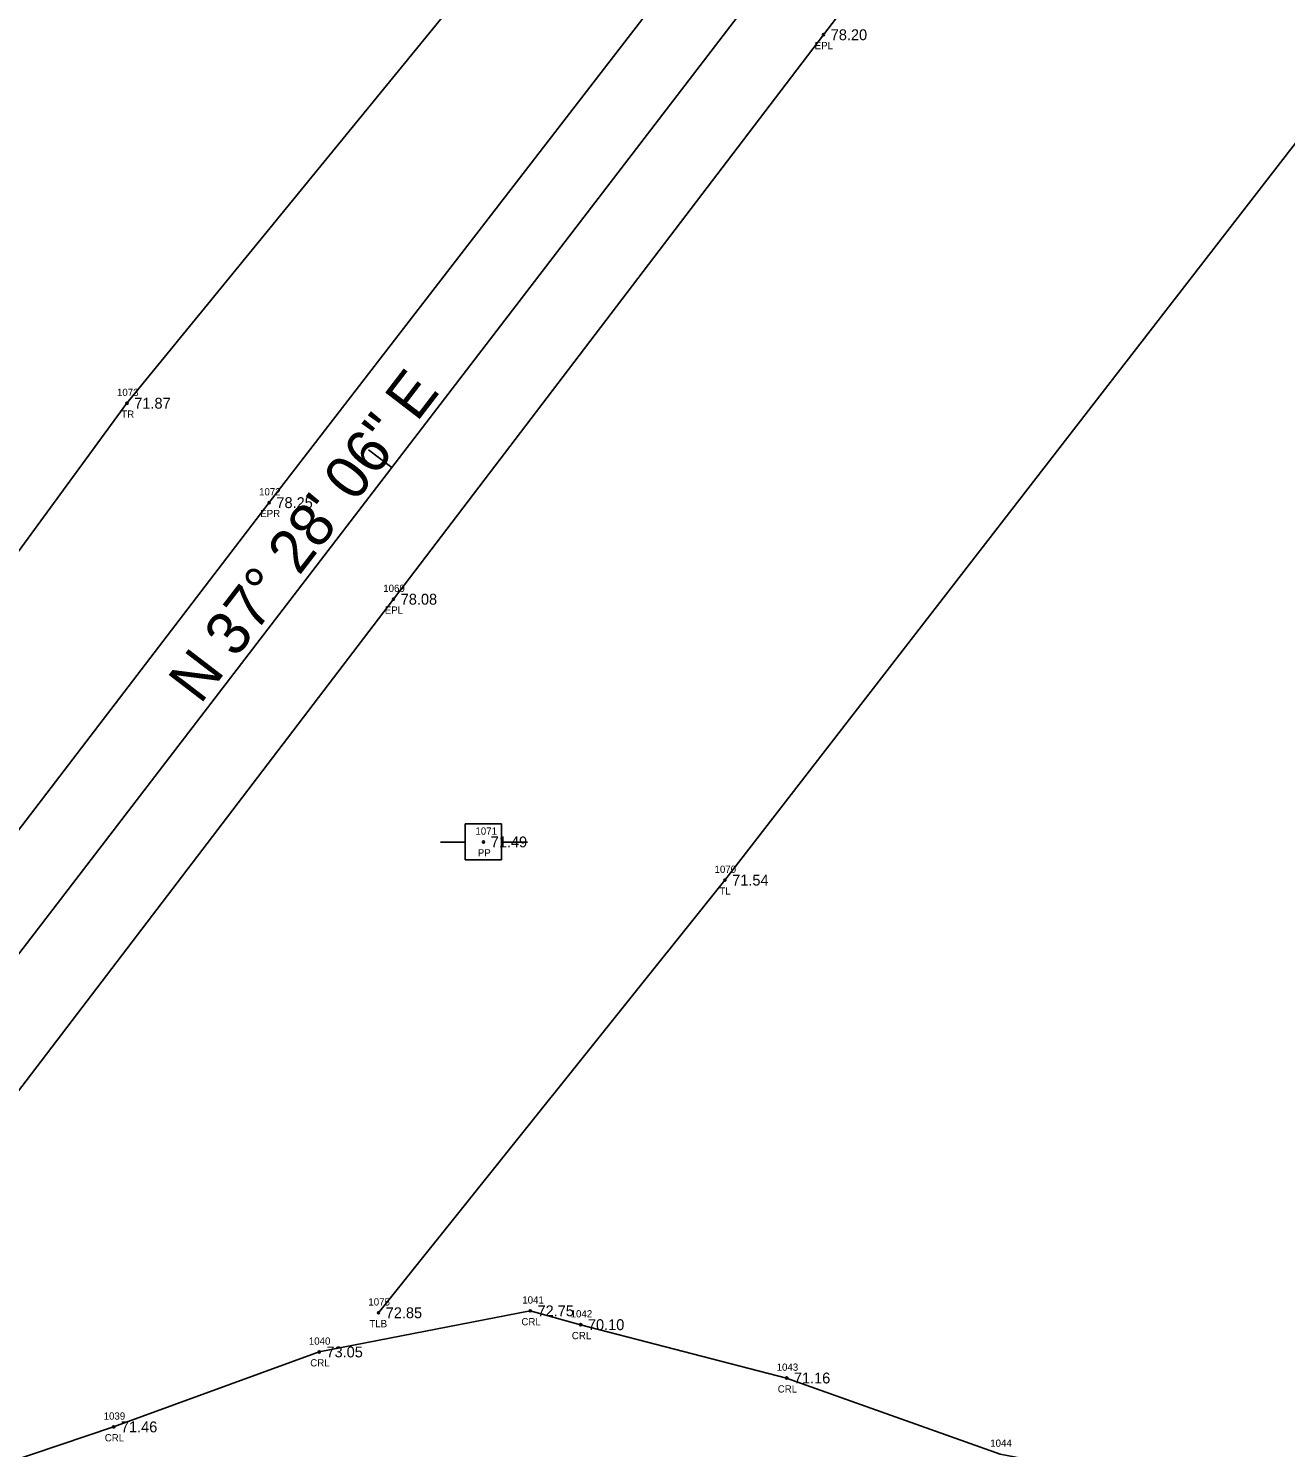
# Model space of a CAD drawing. Extents: x 2505249 to 2506333, y 912937 to 914171.
# Drawn here: x 2505870.1 to 2506043.4, y 913525.6 to 913721.3 of the extents above; entities that cross this region are included whole.
import ezdxf

# ---------------------------------------------------------------- set-up
doc = ezdxf.new("R2010")
doc.units = 0
for name, color, linetype in [('RD_EX_H2O', 7, 'Continuous'), ('RD_EX_H2O_txCode', 7, 'Continuous'), ('RD_EX_Road', 7, 'Continuous'), ('RD_EX_Road_txCode', 7, 'Continuous'), ('RD_EX_TX_H2O_ELEV', 7, 'Continuous'), ('RD_EX_TX_Road_ELEV', 7, 'Continuous'), ('RD_EX_TX_VEG_ELEV', 7, 'Continuous'), ('RD_EX_UT', 7, 'Continuous'), ('RD_EX_UT_txCode', 7, 'Continuous'), ('RD_EX_VEG', 7, 'Continuous'), ('RD_EX_VEG_txCode', 7, 'Continuous'), ('RD_HC_Cl', 7, 'Continuous'), ('RD_HC_Data', 7, 'Continuous'), ('RD_HC_Data_Tic', 7, 'Continuous'), ('RD_HC_Survey_ELEV', 7, 'Continuous'), ('RD_SMD_Locator', 7, 'Continuous')]:
    doc.layers.add(name, color=color, linetype=linetype)

msp = doc.modelspace()

# ---------------------------------------------------------------- linework, layer by layer
at = {"layer": 'RD_EX_H2O'}
msp.add_lwpolyline([(2505762.26, 913658.11), (2505746.15, 913644.25), (2505726.47, 913615.21), (2505674.21, 913628.01), (2505666.25, 913620.58), (2505714.6, 913592.15), (2505793.9, 913560.45), (2505801.32, 913552.8), (2505803.7, 913539.77), (2505832.63, 913516.96), (2505848.42, 913517.19), (2505881.86, 913528.44), (2505910.2, 913538.78), (2505939.3, 913544.45), (2505946.25, 913542.54), (2505974.65, 913535.18), (2506004.11, 913524.7), (2506052.03, 913515.47), (2506115.49, 913494.68), (2506138.05, 913548.89)], dxfattribs=at)
at = {"layer": 'RD_EX_Road'}
for points in [[(2506024.03, 913813.1), (2505962.01, 913732.06), (2505903.3, 913655.93), (2505840.88, 913574.4), (2505819.41, 913546.54), (2505814.19, 913542.64)], [(2506040.71, 913800.23), (2505979.73, 913720.47), (2505920.44, 913642.61), (2505859.42, 913562.61), (2505835.44, 913531.43), (2505833.77, 913527.25)]]:
    msp.add_lwpolyline(points, dxfattribs=at)
at = {"layer": 'RD_EX_UT'}
for p, q in [((2505935.34, 913611.64), (2505930.34, 913611.64)), ((2505930.34, 913611.64), (2505930.34, 913606.64)), ((2505935.34, 913606.64), (2505935.34, 913611.64)), ((2505926.91, 913609.08), (2505930.38, 913609.08)), ((2505935.27, 913609.08), (2505938.91, 913609.08)), ((2505930.34, 913606.64), (2505935.34, 913606.64))]:
    msp.add_line(p, q, dxfattribs=at)
at = {"layer": 'RD_EX_VEG'}
for points in [[(2506002.64, 913815.25), (2505883.7, 913669.64), (2505827.83, 913593.29), (2505814.43, 913589.15), (2505792.49, 913560.55), (2505725.64, 913468.24), (2505664.37, 913399.09), (2505478.33, 913221), (2505411.99, 913152.19), (2505339.13, 913074.53)], [(2506132.67, 913791.11), (2506063.24, 913729.37), (2505966.14, 913603.86), (2505918.37, 913544.18)]]:
    msp.add_lwpolyline(points, dxfattribs=at)
at = {"layer": 'RD_HC_Cl'}
msp.add_line((2505792.76, 913494.51), (2506032.34, 913807.1), dxfattribs=at)
at = {"layer": 'RD_HC_Data_Tic'}
msp.add_line((2505920.2, 913660.78), (2505917.02, 913663.21), dxfattribs=at)
at = {"layer": 'RD_SMD_Locator'}
for centre in [(2505979.73, 913720.47), (2505883.7, 913669.64), (2505903.3, 913655.93), (2505920.44, 913642.61), (2505932.85, 913609.13), (2505966.14, 913603.86), (2505918.37, 913544.18), (2505939.3, 913544.45), (2505946.25, 913542.54), (2505910.2, 913538.78), (2505974.65, 913535.18), (2505881.86, 913528.44)]:
    msp.add_circle(centre, 0.15, dxfattribs=at)

# ---------------------------------------------------------------- texts
at = {"layer": 'RD_EX_H2O_txCode'}
for s, p in [('1041', (2505938.2, 913545.45)), ('1042', (2505944.87, 913543.54)), ('CRL', (2505938.08, 913542.45)), ('1040', (2505908.77, 913539.78)), ('CRL', (2505945.03, 913540.54)), ('CRL', (2505908.97, 913536.78)), ('1043', (2505973.27, 913536.18)), ('CRL', (2505973.42, 913533.18)), ('1039', (2505880.48, 913529.44)), ('CRL', (2505880.63, 913526.44)), ('1044', (2506002.72, 913525.7))]:
    msp.add_text(s, height=1, dxfattribs=at).set_placement(p)
at = {"layer": 'RD_EX_Road_txCode'}
for s, p in [('EPL', (2505978.52, 913718.47)), ('1072', (2505901.91, 913656.93)), ('EPR', (2505902.07, 913653.93)), ('1069', (2505919.03, 913643.61)), ('EPL', (2505919.24, 913640.61))]:
    msp.add_text(s, height=1, dxfattribs=at).set_placement(p)
at = {"layer": 'RD_EX_TX_H2O_ELEV'}
for s, p in [('72.75', (2505940.3, 913543.7)), ('70.10', (2505947.25, 913541.79)), ('73.05', (2505911.2, 913538.03)), ('71.16', (2505975.65, 913534.43)), ('71.46', (2505882.86, 913527.69))]:
    msp.add_text(s, height=1.5, dxfattribs=at).set_placement(p)
at = {"layer": 'RD_EX_TX_Road_ELEV'}
for s, p in [('78.20', (2505980.73, 913719.72)), ('78.25', (2505904.3, 913655.18)), ('78.08', (2505921.44, 913641.86))]:
    msp.add_text(s, height=1.5, dxfattribs=at).set_placement(p)
at = {"layer": 'RD_EX_TX_VEG_ELEV'}
for s, p in [('71.87', (2505884.7, 913668.89)), ('71.54', (2505967.14, 913603.11)), ('72.85', (2505919.37, 913543.43))]:
    msp.add_text(s, height=1.5, dxfattribs=at).set_placement(p)
at = {"layer": 'RD_EX_UT_txCode'}
for s, p in [('1071', (2505931.74, 913610.13)), ('PP', (2505932.07, 913607.13))]:
    msp.add_text(s, height=1, dxfattribs=at).set_placement(p)
at = {"layer": 'RD_EX_VEG_txCode'}
for s, p in [('1073', (2505882.32, 913670.64)), ('TR', (2505882.91, 913667.64)), ('1070', (2505964.71, 913604.86)), ('TL', (2505965.37, 913601.86)), ('1075', (2505916.98, 913545.18)), ('TLB', (2505917.12, 913542.18))]:
    msp.add_text(s, height=1, dxfattribs=at).set_placement(p)
at = {"layer": 'RD_HC_Data'}
msp.add_text('N 37%%d 28\' 06" E', height=6, rotation=52.5316, dxfattribs=at).set_placement((2505893.81, 913627.99))
at = {"layer": 'RD_HC_Survey_ELEV'}
msp.add_text('71.49', height=1.5, dxfattribs=at).set_placement((2505933.85, 913608.38))

doc.saveas('drawing.dxf')
